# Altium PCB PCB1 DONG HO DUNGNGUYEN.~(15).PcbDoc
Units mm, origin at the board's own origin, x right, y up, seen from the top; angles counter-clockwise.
Board outline 54.94 x 47.62 mm, 2 copper layers (Top Layer, Bottom Layer); 8 components, 16 nets, 39 pads, 0 vias.
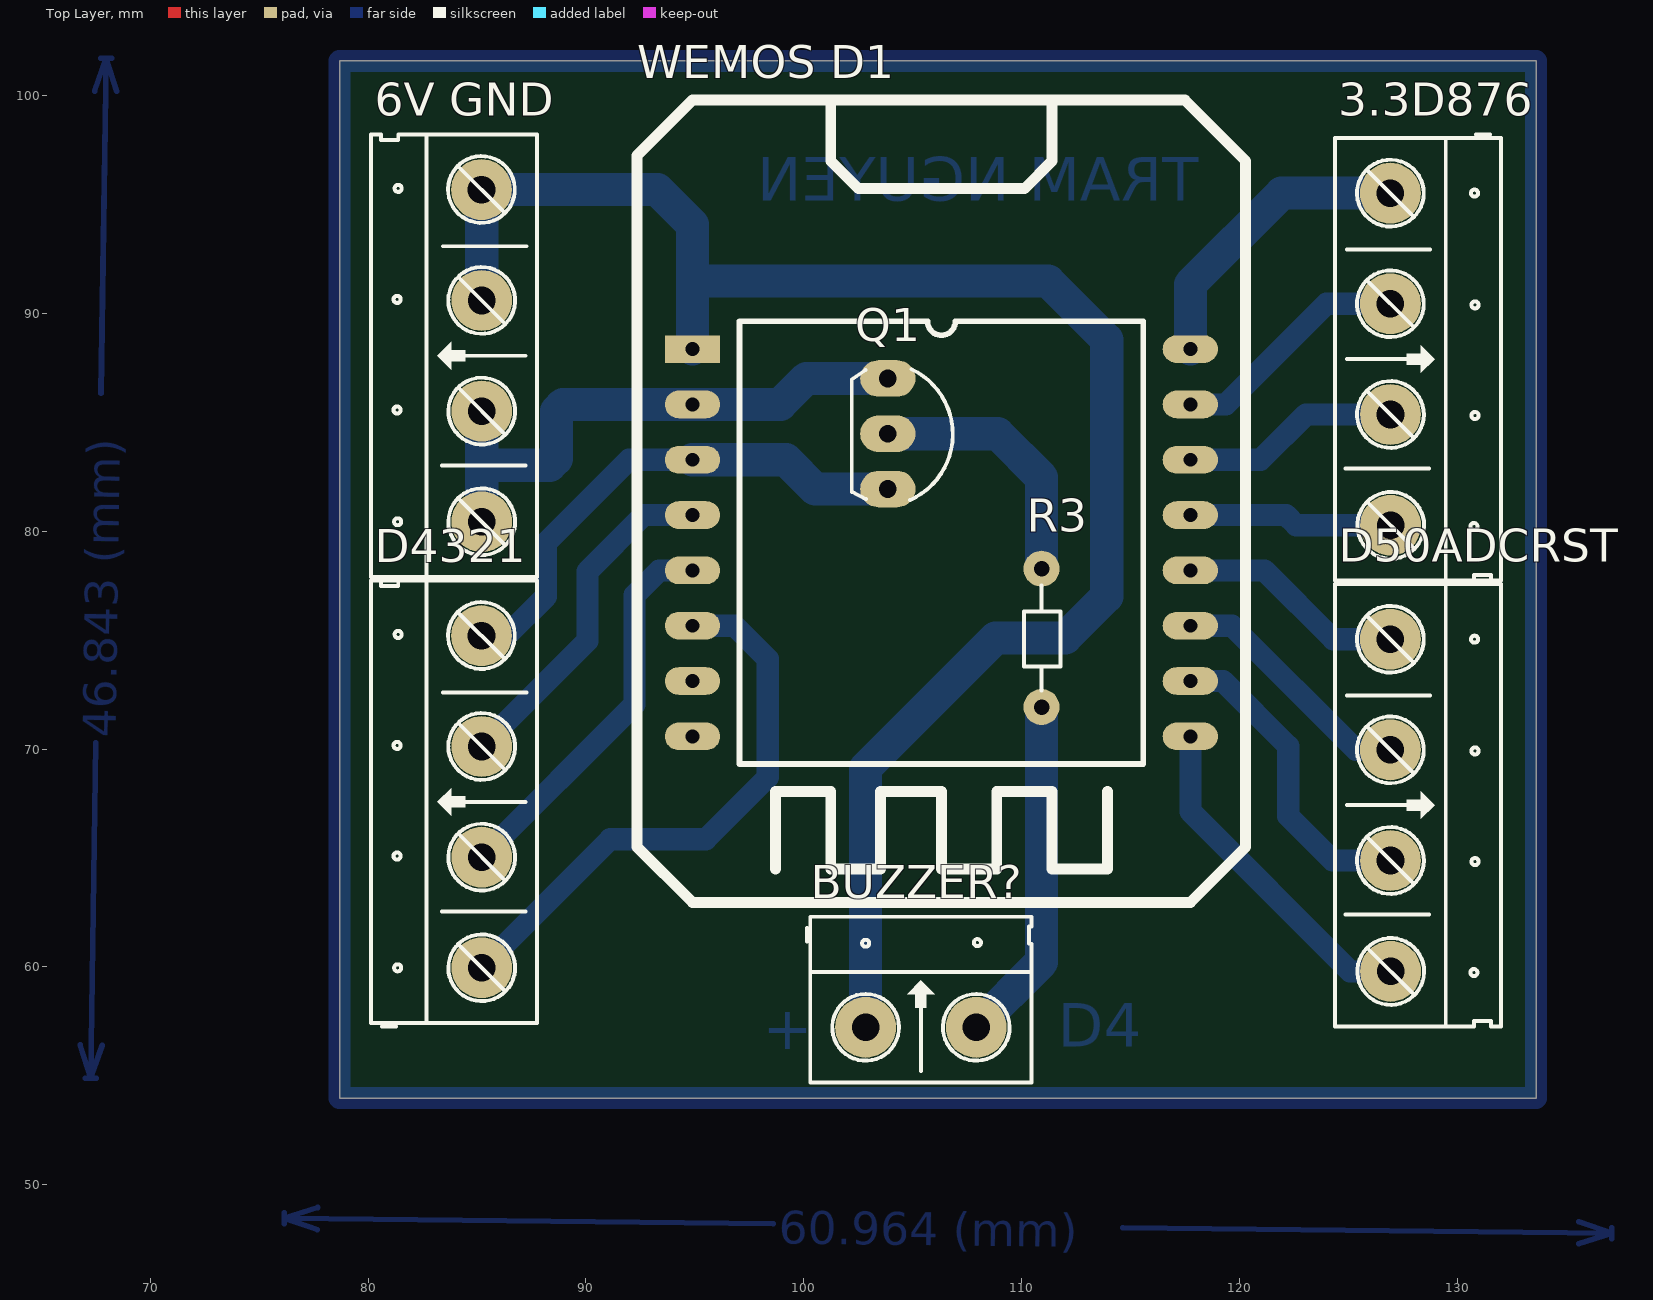
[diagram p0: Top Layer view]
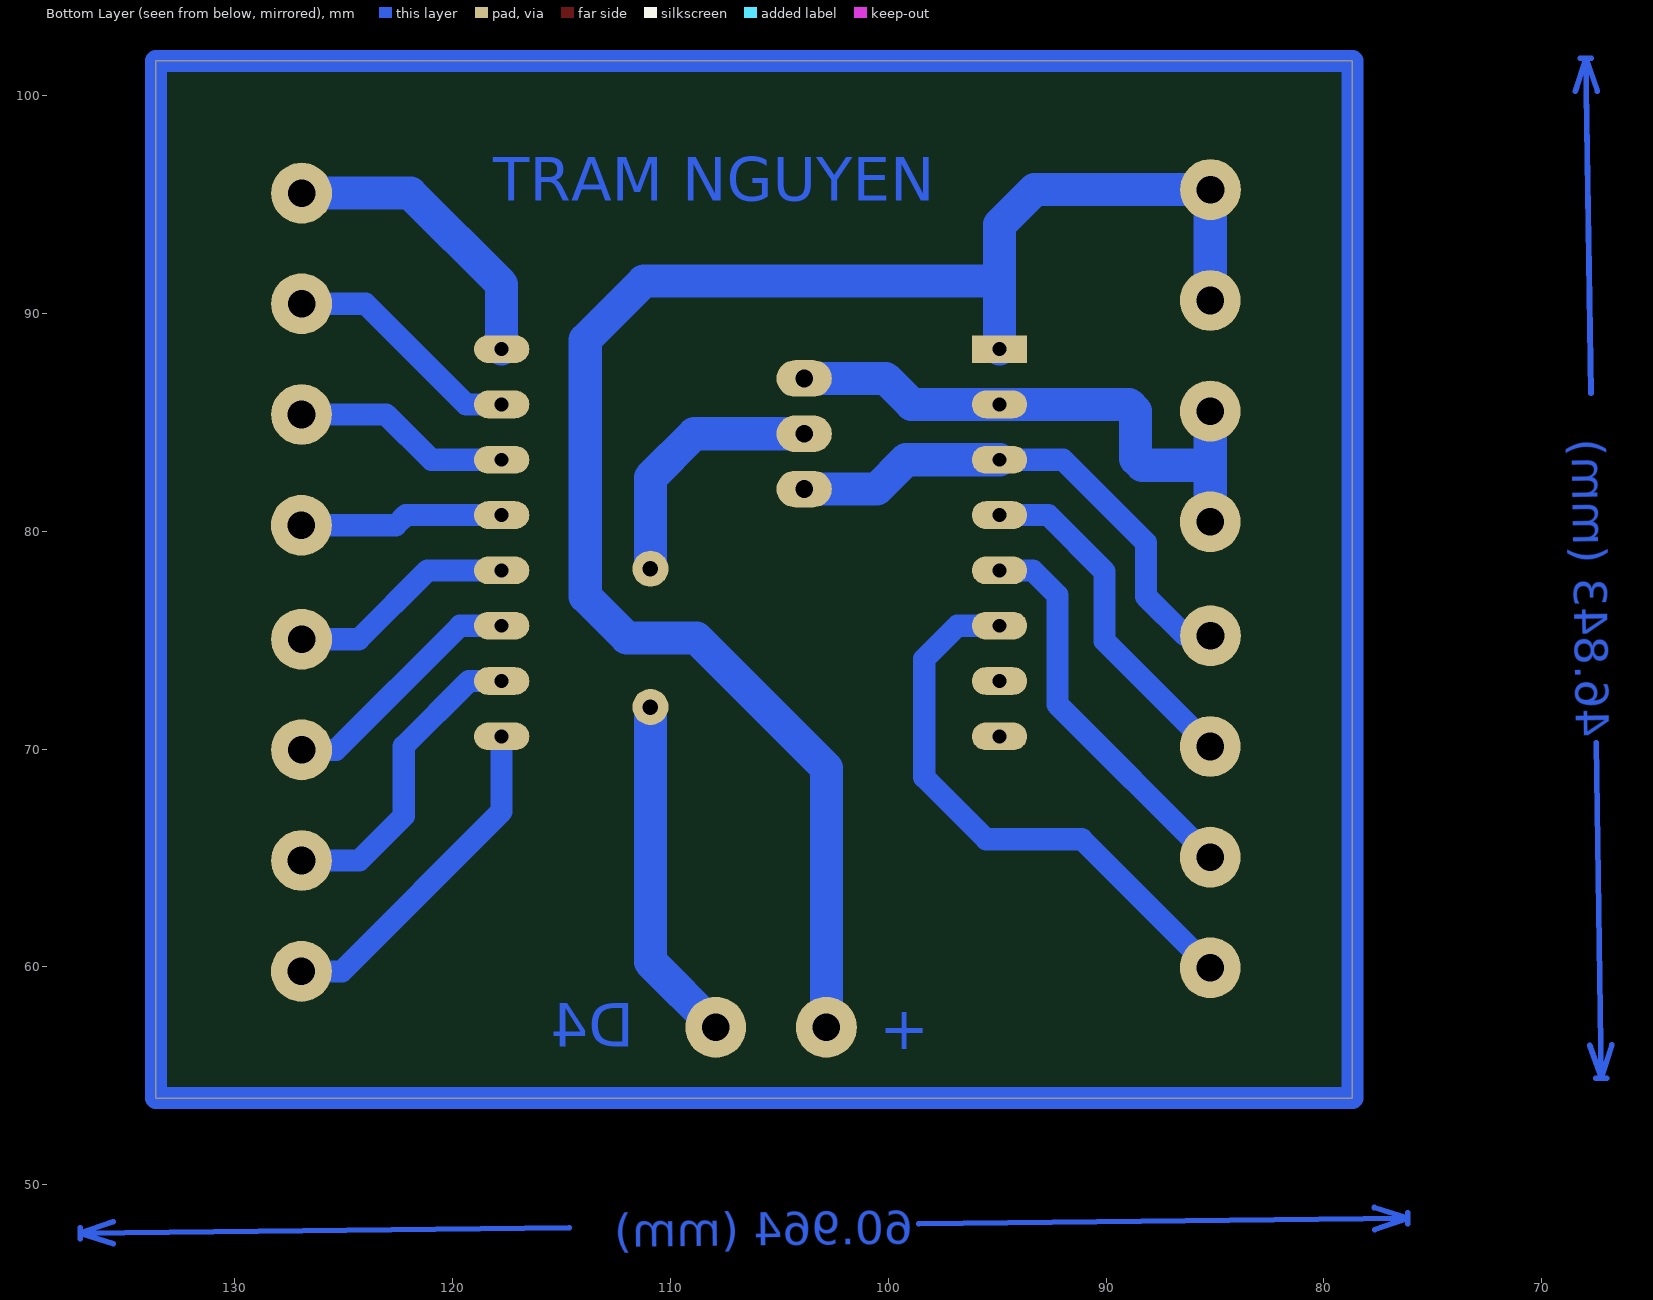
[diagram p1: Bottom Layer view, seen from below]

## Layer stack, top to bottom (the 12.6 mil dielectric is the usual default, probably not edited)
Top Solder: solder mask 0.0102, Solder Resist, Dk 3.5
Top Layer: signal copper 0.0356
Dielectric 1: dielectric 0.32, FR-4, Dk 4.8
Bottom Layer: signal copper 0.0356
Bottom Solder: solder mask 0.0102, Solder Resist, Dk 3.5

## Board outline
78.689,53.975 78.689,101.6 133.629,101.6 133.629,53.975

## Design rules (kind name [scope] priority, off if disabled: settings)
Clearance [All] p1: gap=0.254 ignorepadtopadclearanceinfootprint=FALSE except(0: Arc-Hole Track-Hole SMDPad-Hole THPad-Hole Via-Hole Fill-Hole Poly-Hole Region-Hole Text-Hole)
PolygonConnect [All] p1: connectstyle=Relief reliefconductorwidth=0.254 reliefentries=4 polygonreliefangle="90 Angle" airgapwidth=0.254
RoomDefinition DONG_HO [InComponentClass('DONG_HO')] p1: confinementstyle=ConfineIn formatcopy=TRUE lockcomponents=FALSE outline 138.303,57.277 149.25,57.277 149.25,67.132 138.303,67.132
RoutingVias [All] p1: holewidth=0.711 width=1.27 viastyle="Through Hole" minholewidth=0.711 minwidth=1.27 maxholewidth=2.54 maxwidth=2.54
SolderMaskExpansion [All] p1: expansion=0.102
Width [All] p1: maxlimit=2.032 minlimit=1.016 preferedwidth=1.524
30 further rules are at their usual default settings.

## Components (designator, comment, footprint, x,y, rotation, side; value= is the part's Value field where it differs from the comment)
3.3D876 "Header 4" HED4 126.939,95.528 r270 top
"6V GND" "Header 4" HED4 85.219,80.44 r90 top
BUZZER? "Header 2" HED2 102.845,57.226 r0 top
D50ADCRST "Header 4" HED4 126.939,75.047 r270 top
D4321 "Header 4" HED4 85.219,59.959 r90 top
Q1 "C1815" QTO-92 103.861,84.48 r270 top
R3 "100" RES-1/8W-SMALL 110.922,75.108 r270 top
"WEMOS D1" "Component_1" "ESP WEMOS MINI" 94.894,88.367 r0 top

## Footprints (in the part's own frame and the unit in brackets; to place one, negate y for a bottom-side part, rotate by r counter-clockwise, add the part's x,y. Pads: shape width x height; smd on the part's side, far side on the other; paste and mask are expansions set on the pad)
"ESP WEMOS MINI" [mm]
  rect 2.54x1.27 hole 0.635: 1(0,0)
  oval 2.54x1.27 hole 0.635: 2(0,-2.54) 3(0,-5.08) 4(0,-7.62) 5(0,-10.16) 6(0,-12.7) 7(0,-15.24) 8(0,-17.78) 9(22.86,-17.78) 10(22.86,-15.24) 11(22.86,-12.7) 12(22.86,-10.16) 13(22.86,-7.62) 14(22.86,-5.08) 15(22.86,-2.54) 16(22.86,0)
  silkscreen extent -2.54,-25.4 25.4,11.43
HED2 [mil] "Header 2, 2 pin, hight 300mil, Pin to Pin 200, Colour Green"
  round 110 hole 50: 1(0,0) 2(200,0)
  silkscreen extent -106,-100 300,200, body extent -92,-140 302,155, height 394
HED4 [mil] "Header 4, 4 pin, hight 300mil, Pin to Pin 200, Colour Green"
  round 110 hole 50: 1(0,0) 2(200,0) 3(400.06,0.06) 4(600.39,0.39)
  silkscreen extent -106,-100 700,200
QTO-92 [mil] "TO-92"
  oval 66x100 hole 32: 1(-100,0) 2(0,0) 3(100,0)
  silkscreen extent -117,-65 120,118, body extent -109,-66 109,95, height 245
RES-1/8W-SMALL [mil] "R 1/8W, 2 pin, 200mil"
  round 65 hole 28: 1(-125,0) 2(125,0)
  silkscreen extent -95,-32 95,34, body extent -135,-35 135,37, height 76

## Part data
3.3D876 "6V GND" D50ADCRST D4321: library part Hed4, "Header 4 (Green)"
BUZZER?: library part Hed2, "Header 2 (Green)"
Q1: "NPN 600mW, ECB"
R3: library part Res, "Res", Manufacturer="Generic Components"

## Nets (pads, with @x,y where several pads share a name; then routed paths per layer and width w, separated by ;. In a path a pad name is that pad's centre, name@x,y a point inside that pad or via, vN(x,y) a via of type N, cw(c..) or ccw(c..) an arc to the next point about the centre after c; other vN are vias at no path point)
D4: "WEMOS D1.3" D4321.4 Q1.3 | length 24
  Bottom Layer w1.016: D4321.4 86.36,75.209 88.163,77.013 88.163,79.477 91.973,83.287 94.894,83.287
  Bottom Layer w1.524: 94.894,83.287 99.187,83.287 100.533,81.94 Q1.3
GND: "6V GND.1" "6V GND.2" "WEMOS D1.2" Q1.1 | length 26.7
  Bottom Layer w1.524: 85.219,80.44 85.219,83.033 ; 85.219,85.52 85.219,83.033 ; Q1.1 100.127,87.02 98.933,85.827 94.894,85.827 88.951,85.827 88.644,85.52 88.644,83.336 88.341,83.033 85.219,83.033
Net3.3D876_1: 3.3D876.1 "WEMOS D1.16" | length 13.9
  Bottom Layer w1.524: 117.754,88.367 117.754,91.338 121.944,95.528 3.3D876.1
Net3.3D876_2: 3.3D876.2 "WEMOS D1.15" | length 11.1
  Bottom Layer w1.016: 117.754,85.827 119.38,85.827 124.001,90.448 3.3D876.2
Net3.3D876_3: 3.3D876.3 "WEMOS D1.14" | length 10
  Bottom Layer w1.016: 117.754,83.287 120.98,83.287 123.06,85.366 3.3D876.3
Net3.3D876_4: 3.3D876.4 "WEMOS D1.13" | length 9.4
  Bottom Layer w1.016: 117.754,80.747 122.149,80.747 122.617,80.278 3.3D876.4
NetBUZZER?_2: BUZZER?.2 R3.2 | length 15.9
  Bottom Layer w1.524: BUZZER?.2 110.922,60.223 R3.2
NetD50ADCRST_1: "WEMOS D1.12" D50ADCRST.1 | length 10.5
  Bottom Layer w1.016: 117.754,78.207 121.158,78.207 124.318,75.047 D50ADCRST.1
NetD50ADCRST_2: "WEMOS D1.11" D50ADCRST.2 | length 11.5
  Bottom Layer w1.016: 117.754,75.667 119.659,75.667 125.359,69.967 D50ADCRST.2
NetD50ADCRST_3: "WEMOS D1.10" D50ADCRST.3 | length 14.5
  Bottom Layer w1.016: 117.754,73.127 119.253,73.127 122.25,70.129 122.25,66.929 124.294,64.885 D50ADCRST.3
NetD50ADCRST_4: "WEMOS D1.9" D50ADCRST.4 | length 15.7
  Bottom Layer w1.016: 117.754,70.587 117.754,67.132 125.09,59.797 D50ADCRST.4
NetD4321_1: "WEMOS D1.6" D4321.1 | length 26.3
  Bottom Layer w1.016: D4321.1 91.121,65.862 95.504,65.862 98.349,68.707 98.349,74.143 96.825,75.667 94.894,75.667
NetD4321_2: "WEMOS D1.5" D4321.2 | length 18.1
  Bottom Layer w1.016: D4321.2 92.227,72.048 92.227,77.064 93.37,78.207 94.894,78.207
NetD4321_3: "WEMOS D1.4" D4321.3 | length 15.9
  Bottom Layer w1.016: D4321.3 90.068,74.972 90.068,78.156 92.659,80.747 94.894,80.747
NetQ1_2: Q1.2 R3.1 | length 12.1
  Bottom Layer w1.524: Q1.2 108.915,84.48 110.922,82.474 R3.1
VCC: "6V GND.3" "6V GND.4" "WEMOS D1.1" BUZZER?.1 | length 79.3
  Bottom Layer w1.524: 85.217,90.602 85.217,95.682 85.209,95.69 93.286,95.69 94.894,94.082 94.894,91.491 ; 94.894,88.367 94.894,91.491 ; BUZZER?.1 102.845,69.139 108.814,75.108 112.014,75.108 113.919,77.013 113.919,88.798 111.227,91.491 94.894,91.491
pads on no net: "WEMOS D1.7" "WEMOS D1.8"
copper on no net: | length 295.7
  Bottom Layer w0.254: 66.774,56.421 67.259,54.889 ; 67.005,54.893 67.513,54.886 ; 67.439,100.211 67.97,101.727 ; 67.493,70.285 67.259,54.889 ; 67.716,101.731 68.224,101.723 ; 67.737,86.331 67.97,101.727 ; 67.79,56.406 67.259,54.889 ; 68.455,100.195 67.97,101.727 ; 76.146,48.209 76.152,48.717 ; 77.667,47.938 76.149,48.463 ; 77.679,48.954 76.149,48.463 ; 98.606,48.211 76.149,48.463 ; 114.653,48.03 137.109,47.777 ; 135.58,47.287 137.109,47.777 ; 135.591,48.303 137.109,47.777 ; 137.106,47.523 137.112,48.031
  Bottom Layer w1.016: 78.689,53.975 78.689,101.6 133.629,101.6 133.629,53.975 78.689,53.975

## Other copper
Bottom Layer:
  text "TRAM NGUYEN" at 118.135,95.174 h2
  text "46.843 (mm)" at 68.411,70.525 h1.52 r89.13
  text "D4" at 111.658,56.337 h2
  text "+" at 98.12,56.21 h2
  text "60.964 (mm)" at 98.849,47.294 h1.52 r359.36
